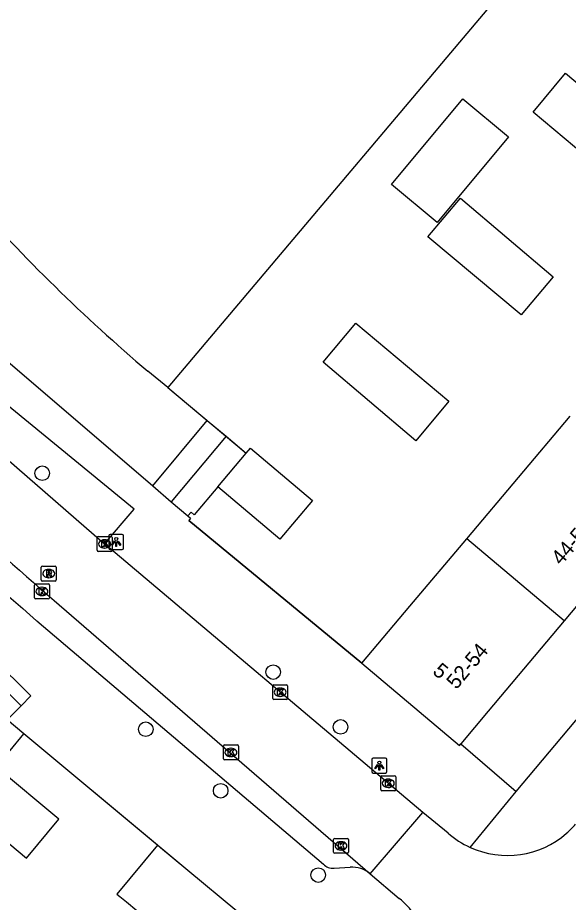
# Model space of a CAD drawing. Extents: x 162532 to 163264, y 381233 to 382042.
# Drawn here: x 162954.6 to 162991.6, y 381669.2 to 381728.5 of the extents above; entities that cross this region are included whole.
import ezdxf

# ---------------------------------------------------------------- set-up
doc = ezdxf.new("R2010")
doc.units = 0
for name, color, linetype in [('IMGEO_Boom', 7, 'Continuous'), ('IMGEO_Groenvoorziening', 7, 'Continuous'), ('IMGEO_Hek', 7, 'Continuous'), ('IMGEO_Kolk', 7, 'Continuous'), ('IMGEO_Lichtpunt', 7, 'Continuous'), ('IMGEO_Muur', 7, 'Continuous'), ('IMGEO_Pand', 7, 'Continuous'), ('IMGEO_Pand_nummerreeks', 7, 'Continuous'), ('IMGEO_Rijbaan_lokaal_open', 7, 'Continuous'), ('IMGEO_Rioolput', 7, 'Continuous'), ('IMGEO_Voetpad_open', 7, 'Continuous')]:
    doc.layers.add(name, color=color, linetype=linetype)

msp = doc.modelspace()

# ---------------------------------------------------------------- linework, layer by layer
at = {"layer": 'IMGEO_Boom'}
for centre in [(162956.297, 381697.954), (162971.791, 381684.612), (162976.31, 381680.937), (162963.243, 381680.782), (162968.27, 381676.657), (162974.813, 381670.995)]:
    msp.add_circle(centre, 0.489, dxfattribs=at)
at = {"layer": 'IMGEO_Groenvoorziening'}
for points in [[(162964.729, 381703.699), (162967.366, 381701.497)], [(162968.629, 381700.443), (162969.987, 381699.309)], [(162968.077, 381697.044), (162966.49, 381695.158), (162966.278, 381695.34), (162966.063, 381695.095)]]:
    msp.add_lwpolyline(points, dxfattribs=at)
at = {"layer": 'IMGEO_Hek'}
msp.add_lwpolyline([(162964.729, 381703.699), (162969.987, 381699.309)], dxfattribs=at)
at = {"layer": 'IMGEO_Kolk'}
for p, q in [((162959.977, 381692.785), (162959.977, 381693.637)), ((162960.052, 381693.711), (162960.904, 381693.711)), ((162960.465, 381693.491), (162960.49, 381693.491)), ((162960.978, 381693.637), (162960.978, 381692.785)), ((162960.904, 381692.711), (162960.052, 381692.711)), ((162960.488, 381692.931), (162960.463, 381692.931)), ((162955.776, 381689.603), (162955.776, 381690.455)), ((162955.851, 381690.529), (162956.703, 381690.529)), ((162956.777, 381690.455), (162956.777, 381689.603)), ((162956.287, 381689.749), (162956.262, 381689.749)), ((162956.264, 381690.309), (162956.289, 381690.309)), ((162956.703, 381689.529), (162955.851, 381689.529)), ((162971.758, 381682.841), (162971.758, 381683.693)), ((162971.833, 381683.767), (162972.685, 381683.767)), ((162972.246, 381683.547), (162972.271, 381683.547)), ((162972.759, 381683.693), (162972.759, 381682.841)), ((162972.685, 381682.767), (162971.833, 381682.767)), ((162972.269, 381682.987), (162972.244, 381682.987)), ((162968.453, 381678.8), (162968.453, 381679.652)), ((162968.528, 381679.726), (162969.38, 381679.726)), ((162969.454, 381679.652), (162969.454, 381678.8)), ((162968.941, 381679.506), (162968.966, 381679.506)), ((162969.38, 381678.726), (162968.528, 381678.726)), ((162968.964, 381678.946), (162968.939, 381678.946)), ((162979.01, 381676.729), (162979.01, 381677.581)), ((162979.085, 381677.655), (162979.937, 381677.655)), ((162979.498, 381677.435), (162979.523, 381677.435)), ((162980.011, 381677.581), (162980.011, 381676.729)), ((162979.521, 381676.875), (162979.496, 381676.875)), ((162979.937, 381676.655), (162979.085, 381676.655)), ((162975.842, 381672.532), (162975.842, 381673.384)), ((162975.917, 381673.458), (162976.769, 381673.458)), ((162976.33, 381673.238), (162976.355, 381673.238)), ((162976.843, 381673.384), (162976.843, 381672.532)), ((162976.353, 381672.678), (162976.328, 381672.678)), ((162976.769, 381672.458), (162975.917, 381672.458))]:
    msp.add_line(p, q, dxfattribs=at)
for points in [[(162959.977, 381692.785), (162959.977, 381693.637)], [(162960.052, 381693.711), (162960.904, 381693.711)], [(162960.298, 381693.411), (162960.421, 381693.411), (162960.421, 381693.26), (162960.551, 381693.411), (162960.715, 381693.411), (162960.569, 381693.26), (162960.722, 381693.011), (162960.57, 381693.011), (162960.485, 381693.175), (162960.421, 381693.108), (162960.421, 381693.011), (162960.298, 381693.011), (162960.298, 381693.411)], [(162960.978, 381693.637), (162960.978, 381692.785)], [(162960.904, 381692.711), (162960.052, 381692.711)], [(162955.776, 381689.603), (162955.776, 381690.455)], [(162955.851, 381690.529), (162956.703, 381690.529)], [(162956.777, 381690.455), (162956.777, 381689.603)], [(162956.097, 381690.229), (162956.22, 381690.229), (162956.22, 381690.078), (162956.35, 381690.229), (162956.514, 381690.229), (162956.368, 381690.078), (162956.521, 381689.829), (162956.369, 381689.829), (162956.284, 381689.993), (162956.22, 381689.926), (162956.22, 381689.829), (162956.097, 381689.829), (162956.097, 381690.229)], [(162956.703, 381689.529), (162955.851, 381689.529)], [(162971.758, 381682.841), (162971.758, 381683.693)], [(162971.833, 381683.767), (162972.685, 381683.767)], [(162972.079, 381683.467), (162972.202, 381683.467), (162972.202, 381683.316), (162972.332, 381683.467), (162972.496, 381683.467), (162972.35, 381683.316), (162972.503, 381683.067), (162972.351, 381683.067), (162972.266, 381683.231), (162972.202, 381683.164), (162972.202, 381683.067), (162972.079, 381683.067), (162972.079, 381683.467)], [(162972.759, 381683.693), (162972.759, 381682.841)], [(162972.685, 381682.767), (162971.833, 381682.767)], [(162968.453, 381678.8), (162968.453, 381679.652)], [(162968.528, 381679.726), (162969.38, 381679.726)], [(162969.454, 381679.652), (162969.454, 381678.8)], [(162968.774, 381679.426), (162968.897, 381679.426), (162968.897, 381679.275), (162969.027, 381679.426), (162969.191, 381679.426), (162969.045, 381679.275), (162969.198, 381679.026), (162969.046, 381679.026), (162968.961, 381679.19), (162968.897, 381679.123), (162968.897, 381679.026), (162968.774, 381679.026), (162968.774, 381679.426)], [(162969.38, 381678.726), (162968.528, 381678.726)], [(162979.01, 381676.729), (162979.01, 381677.581)], [(162979.085, 381677.655), (162979.937, 381677.655)], [(162979.331, 381677.355), (162979.454, 381677.355), (162979.454, 381677.204), (162979.584, 381677.355), (162979.748, 381677.355), (162979.602, 381677.204), (162979.755, 381676.955), (162979.603, 381676.955), (162979.518, 381677.119), (162979.454, 381677.052), (162979.454, 381676.955), (162979.331, 381676.955), (162979.331, 381677.355)], [(162980.011, 381677.581), (162980.011, 381676.729)], [(162979.937, 381676.655), (162979.085, 381676.655)], [(162975.842, 381672.532), (162975.842, 381673.384)], [(162975.917, 381673.458), (162976.769, 381673.458)], [(162976.163, 381673.158), (162976.286, 381673.158), (162976.286, 381673.007), (162976.416, 381673.158), (162976.58, 381673.158), (162976.434, 381673.007), (162976.587, 381672.758), (162976.435, 381672.758), (162976.35, 381672.922), (162976.286, 381672.855), (162976.286, 381672.758), (162976.163, 381672.758), (162976.163, 381673.158)], [(162976.843, 381673.384), (162976.843, 381672.532)], [(162976.769, 381672.458), (162975.917, 381672.458)]]:
    msp.add_lwpolyline(points, dxfattribs=at)
for centre, start, end in [((162960.054, 381693.635), 91.55205, 178.44795), ((162960.054, 381693.635), 91.55205, 178.44795), ((162960.902, 381693.635), 1.55205, 88.44795), ((162960.902, 381693.635), 1.55205, 88.44795), ((162960.054, 381692.787), 181.55205, 268.44795), ((162960.054, 381692.787), 181.55205, 268.44795), ((162960.902, 381692.787), 271.55205, 358.44795), ((162960.902, 381692.787), 271.55205, 358.44795), ((162955.853, 381690.453), 91.55205, 178.44795), ((162955.853, 381690.453), 91.55205, 178.44795), ((162956.701, 381690.453), 1.55205, 88.44795), ((162956.701, 381690.453), 1.55205, 88.44795), ((162955.853, 381689.605), 181.55205, 268.44795), ((162955.853, 381689.605), 181.55205, 268.44795), ((162956.701, 381689.605), 271.55205, 358.44795), ((162956.701, 381689.605), 271.55205, 358.44795), ((162971.835, 381683.691), 91.55205, 178.44795), ((162971.835, 381683.691), 91.55205, 178.44795), ((162972.683, 381683.691), 1.55205, 88.44795), ((162972.683, 381683.691), 1.55205, 88.44795), ((162971.835, 381682.843), 181.55205, 268.44795), ((162971.835, 381682.843), 181.55205, 268.44795), ((162972.683, 381682.843), 271.55205, 358.44795), ((162972.683, 381682.843), 271.55205, 358.44795), ((162968.53, 381679.65), 91.55205, 178.44795), ((162968.53, 381679.65), 91.55205, 178.44795), ((162969.378, 381679.65), 1.55205, 88.44795), ((162969.378, 381679.65), 1.55205, 88.44795), ((162968.53, 381678.802), 181.55205, 268.44795), ((162968.53, 381678.802), 181.55205, 268.44795), ((162969.378, 381678.802), 271.55205, 358.44795), ((162969.378, 381678.802), 271.55205, 358.44795), ((162979.087, 381677.579), 91.55205, 178.44795), ((162979.087, 381677.579), 91.55205, 178.44795), ((162979.935, 381677.579), 1.55205, 88.44795), ((162979.935, 381677.579), 1.55205, 88.44795), ((162979.087, 381676.731), 181.55205, 268.44795), ((162979.087, 381676.731), 181.55205, 268.44795), ((162979.935, 381676.731), 271.55205, 358.44795), ((162979.935, 381676.731), 271.55205, 358.44795), ((162975.919, 381673.382), 91.55205, 178.44795), ((162975.919, 381673.382), 91.55205, 178.44795), ((162976.767, 381673.382), 1.55205, 88.44795), ((162976.767, 381673.382), 1.55205, 88.44795), ((162975.919, 381672.534), 181.55205, 268.44795), ((162975.919, 381672.534), 181.55205, 268.44795), ((162976.767, 381672.534), 271.55205, 358.44795), ((162976.767, 381672.534), 271.55205, 358.44795)]:
    msp.add_arc(centre, 0.0765, start, end, dxfattribs=at)
for centre, major_axis, ratio, start_param, end_param in [((162960.464, 381693.211), (-0.387, 0.002), 0.722429, 4.712389, 7.853982), ((162960.489, 381693.211), (-0.39, 0.002), 0.717154, 1.570796, 4.712389), ((162956.263, 381690.029), (-0.387, 0.002), 0.722429, 4.712389, 7.853982), ((162956.288, 381690.029), (-0.39, 0.002), 0.717154, 1.570796, 4.712389), ((162972.245, 381683.267), (-0.387, 0.002), 0.722429, 4.712389, 7.853982), ((162972.27, 381683.267), (-0.39, 0.002), 0.717154, 1.570796, 4.712389), ((162968.94, 381679.226), (-0.387, 0.002), 0.722429, 4.712389, 7.853982), ((162968.965, 381679.226), (-0.39, 0.002), 0.717154, 1.570796, 4.712389), ((162979.497, 381677.155), (-0.387, 0.002), 0.722429, 4.712389, 7.853982), ((162979.522, 381677.155), (-0.39, 0.002), 0.717154, 1.570796, 4.712389), ((162976.329, 381672.958), (-0.387, 0.002), 0.722429, 4.712389, 7.853982), ((162976.354, 381672.958), (-0.39, 0.002), 0.717154, 1.570796, 4.712389)]:
    msp.add_ellipse(centre, major_axis=major_axis, ratio=ratio, start_param=start_param, end_param=end_param, dxfattribs=at)
at = {"layer": 'IMGEO_Lichtpunt'}
for p, q in [((162960.762, 381693.746), (162960.762, 381692.939)), ((162960.762, 381693.746), (162960.762, 381692.939)), ((162961.664, 381693.841), (162960.856, 381693.841)), ((162961.664, 381693.841), (162960.856, 381693.841)), ((162961.758, 381692.939), (162961.758, 381693.746)), ((162961.758, 381692.939), (162961.758, 381693.746)), ((162960.856, 381692.845), (162961.664, 381692.845)), ((162960.856, 381692.845), (162961.664, 381692.845)), ((162978.415, 381678.746), (162978.415, 381677.939)), ((162978.415, 381678.746), (162978.415, 381677.939)), ((162979.317, 381678.841), (162978.509, 381678.841)), ((162979.317, 381678.841), (162978.509, 381678.841)), ((162979.411, 381677.939), (162979.411, 381678.746)), ((162979.411, 381677.939), (162979.411, 381678.746)), ((162978.509, 381677.845), (162979.317, 381677.845)), ((162978.509, 381677.845), (162979.317, 381677.845))]:
    msp.add_line(p, q, dxfattribs=at)
for points in [[(162961.136, 381693.41), (162961.175, 381693.382), (162960.987, 381693.12), (162960.949, 381693.147), (162961.136, 381693.41)], [(162961.238, 381693.362), (162961.285, 381693.362), (162961.285, 381693.04), (162961.238, 381693.04), (162961.238, 381693.362)], [(162961.348, 381693.382), (162961.386, 381693.409), (162961.573, 381693.147), (162961.534, 381693.119), (162961.348, 381693.382)], [(162978.789, 381678.41), (162978.828, 381678.382), (162978.64, 381678.12), (162978.602, 381678.147), (162978.789, 381678.41)], [(162978.891, 381678.362), (162978.938, 381678.362), (162978.938, 381678.04), (162978.891, 381678.04), (162978.891, 381678.362)], [(162979.001, 381678.382), (162979.039, 381678.409), (162979.226, 381678.147), (162979.187, 381678.119), (162979.001, 381678.382)]]:
    msp.add_lwpolyline(points, dxfattribs=at)
for centre in [(162961.261, 381693.544), (162978.914, 381678.544)]:
    msp.add_circle(centre, 0.0994, dxfattribs=at)
for centre, start, end in [((162960.856, 381693.746), 90, 180), ((162960.856, 381693.746), 90, 180), ((162961.664, 381693.746), 0, 90), ((162961.664, 381693.746), 0, 90), ((162960.856, 381692.939), 180, 270), ((162960.856, 381692.939), 180, 270), ((162961.664, 381692.939), 270, 0), ((162961.664, 381692.939), 270, 360), ((162978.509, 381678.746), 90, 180), ((162978.509, 381678.746), 90, 180), ((162979.317, 381678.746), 0, 90), ((162979.317, 381678.746), 0, 90), ((162978.509, 381677.939), 180, 270), ((162978.509, 381677.939), 180, 270), ((162979.317, 381677.939), 270, 0), ((162979.317, 381677.939), 270, 360)]:
    msp.add_arc(centre, 0.0946, start, end, dxfattribs=at)
at = {"layer": 'IMGEO_Muur'}
for points in [[(162977.742, 381685.21), (162966.124, 381694.794)], [(162966.065, 381671.316), (162955.064, 381680.47)]]:
    msp.add_lwpolyline(points, dxfattribs=at)
at = {"layer": 'IMGEO_Pand'}
for points in [[(162990.383, 381734.099), (162964.729, 381703.699)], [(162997.661, 381719.549), (162995.476, 381716.943), (162989.231, 381722.179), (162991.415, 381724.785), (162997.661, 381719.549)], [(162982.794, 381714.785), (162979.737, 381717.33), (162984.52, 381723.075), (162987.577, 381720.53), (162982.794, 381714.785)], [(162990.582, 381711.134), (162988.424, 381708.591), (162982.168, 381713.814), (162984.367, 381716.407), (162990.582, 381711.134)], [(162983.586, 381702.793), (162981.368, 381700.134), (162975.15, 381705.403), (162977.328, 381708.014), (162983.586, 381702.793)], [(162964.729, 381703.699), (162963.382, 381704.799)], [(162984.774, 381693.548), (162991.713, 381701.775)], [(162969.987, 381699.309), (162970.265, 381699.638), (162974.431, 381696.124), (162972.243, 381693.53), (162968.077, 381697.044)], [(162968.077, 381697.044), (162969.987, 381699.309)], [(162998.234, 381696.283), (162991.307, 381688.047)], [(162977.742, 381685.21), (162980.965, 381689.033), (162984.774, 381693.548)], [(162991.307, 381688.047), (162984.774, 381693.548)], [(162991.307, 381688.047), (162986.216, 381681.994), (162984.377, 381679.811)], [(162954.879, 381682.353), (162950.585, 381686.607)], [(162977.742, 381685.21), (162984.283, 381679.699), (162984.377, 381679.811)], [(162953.935, 381681.41), (162954.879, 381682.353)], [(162951.04, 381675.633), (162955.245, 381672.135), (162957.413, 381674.741), (162953.208, 381678.239)], [(162964.038, 381673.002), (162961.309, 381669.723), (162961.513, 381669.553), (162961.939, 381669.199), (162963.336, 381668.037), (162959.478, 381663.4)], [(162972.63, 381665.855), (162966.065, 381671.316), (162964.242, 381672.832), (162964.038, 381673.002)]]:
    msp.add_lwpolyline(points, dxfattribs=at)
msp.add_arc((163040.327, 381795.497), 118.939, 221.57083, 229.68985, dxfattribs=at)
at = {"layer": 'IMGEO_Rijbaan_lokaal_open'}
for points in [[(162936.622, 381716.371), (162938.106, 381714.679), (162947.991, 381704.075), (162960.478, 381693.211)], [(162981.843, 381675.2), (162960.478, 381693.211)], [(162957.099, 381689.422), (162978.305, 381671.073)], [(162978.305, 381671.073), (162981.843, 381675.2)], [(162983.522, 381673.814), (162981.843, 381675.2)], [(162978.305, 381671.073), (162980.244, 381669.431)]]:
    msp.add_lwpolyline(points, dxfattribs=at)
for centre, radius, start, end in [((163191.822, 381961.768), 359.537, 226.1006, 229.24335), ((162987.545, 381678.298), 5.968, 311.14455, 319.41994), ((162987.469, 381678.283), 5.962, 228.54989, 245.58193), ((162987.503, 381678.333), 6.022, 245.48188, 311.22949), ((162976.477, 381664.764), 5.997, 36.51494, 51.08809)]:
    msp.add_arc(centre, radius, start, end, dxfattribs=at)
at = {"layer": 'IMGEO_Rioolput'}
for p, q in [((162956.235, 381690.797), (162956.235, 381691.649)), ((162956.31, 381691.723), (162957.162, 381691.723)), ((162957.236, 381691.649), (162957.236, 381690.797)), ((162956.746, 381690.943), (162956.721, 381690.943)), ((162956.723, 381691.503), (162956.748, 381691.503)), ((162957.162, 381690.723), (162956.31, 381690.723))]:
    msp.add_line(p, q, dxfattribs=at)
for points in [[(162956.235, 381690.797), (162956.235, 381691.649)], [(162956.31, 381691.723), (162957.162, 381691.723)], [(162957.236, 381691.649), (162957.236, 381690.797)], [(162956.824, 381691.421), (162956.572, 381691.423), (162956.572, 381691.023)], [(162956.572, 381691.023), (162956.696, 381691.023), (162956.696, 381691.185), (162956.707, 381691.185)], [(162956.75, 381691.342), (162956.696, 381691.342), (162956.696, 381691.261)], [(162956.696, 381691.261), (162956.748, 381691.261)], [(162956.754, 381691.156), (162956.825, 381691.023), (162956.965, 381691.023), (162956.9, 381691.149)], [(162957.162, 381690.723), (162956.31, 381690.723)]]:
    msp.add_lwpolyline(points, dxfattribs=at)
for centre, radius, start, end in [((162956.312, 381691.647), 0.0765, 91.55205, 178.44795), ((162956.312, 381691.647), 0.0765, 91.55205, 178.44795), ((162957.16, 381691.647), 0.0765, 1.55205, 88.44795), ((162957.16, 381691.647), 0.0765, 1.55205, 88.44795), ((162956.706, 381691.132), 0.0533, 26.02933, 88.69889), ((162956.732, 381691.45), 0.19, 274.7715, 282.96867), ((162956.756, 381691.246), 0.0964, 77.00612, 93.18647), ((162956.77, 381691.303), 0.0378, 276.66336, 79.67722), ((162956.823, 381691.311), 0.109, 350.36119, 89.41601), ((162956.821, 381691.311), 0.112, 277.58423, 350.98172), ((162956.805, 381691.096), 0.108, 29.51342, 73.79051), ((162956.312, 381690.799), 0.0765, 181.55205, 268.44795), ((162956.312, 381690.799), 0.0765, 181.55205, 268.44795), ((162957.16, 381690.799), 0.0765, 271.55205, 358.44795), ((162957.16, 381690.799), 0.0765, 271.55205, 358.44795)]:
    msp.add_arc(centre, radius, start, end, dxfattribs=at)
for centre, major_axis, ratio, start_param, end_param in [((162956.722, 381691.223), (-0.387, 0.002), 0.722429, 4.712389, 7.853982), ((162956.747, 381691.223), (-0.39, 0.002), 0.717154, 1.570796, 4.712389)]:
    msp.add_ellipse(centre, major_axis=major_axis, ratio=ratio, start_param=start_param, end_param=end_param, dxfattribs=at)
at = {"layer": 'IMGEO_Voetpad_open'}
for points in [[(162988.098, 381676.598), (163000, 381690.752), (163049.821, 381750), (163057.405, 381759.019), (163056.336, 381759.96), (163057.544, 381761.374)], [(162960.478, 381693.211), (162962.456, 381695.546), (162953.361, 381702.985), (162947.575, 381708.177), (162939.183, 381717.335), (162933.55, 381724.731), (162930.331, 381730.383), (162928.221, 381736.339), (162926.453, 381736.002)], [(162934.409, 381727.381), (162938.236, 381721.876), (162944.337, 381714.615), (162947.68, 381711.099), (162950.994, 381708.006), (162963.707, 381697.114)], [(162954.879, 381682.353), (162955.541, 381683.015), (162922.637, 381715.61), (162921.981, 381714.947)], [(162963.707, 381697.114), (162967.366, 381701.497)], [(162967.366, 381701.497), (162968.629, 381700.443)], [(162968.629, 381700.443), (162964.956, 381696.043)], [(162963.707, 381697.114), (162964.956, 381696.043)], [(162964.956, 381696.043), (162966.063, 381695.095)], [(162966.063, 381695.095), (162966.243, 381694.942), (162966.124, 381694.794), (162977.742, 381685.21)], [(162955.923, 381688.059), (162975.159, 381671.724)], [(162955.064, 381680.47), (162953.935, 381681.41)], [(162953.208, 381678.239), (162955.064, 381680.47)], [(162964.038, 381673.002), (162955.064, 381680.47)], [(162984.377, 381679.811), (162988.098, 381676.598)], [(162985.004, 381672.854), (162988.098, 381676.598)], [(162975.872, 381671.455), (162976.957, 381671.528)]]:
    msp.add_lwpolyline(points, dxfattribs=at)
for centre, radius, start, end in [((163192.817, 381962.862), 362.816, 226.10415, 229.23694), ((162975.828, 381672.418), 0.964, 226.05396, 272.60515), ((162977.061, 381669.613), 1.918, 49.58206, 93.11505)]:
    msp.add_arc(centre, radius, start, end, dxfattribs=at)

# ---------------------------------------------------------------- texts
at = {"layer": 'IMGEO_Pand_nummerreeks'}
for s, rotation, p in [('44-50', 49.39871, (162991.11, 381691.728)), ('52-54', 49.95326, (162984.088, 381683.404)), ('5', 319.8848, (162982.426, 381684.559))]:
    msp.add_text(s, height=1, rotation=rotation, dxfattribs=at).set_placement(p)

doc.saveas('drawing.dxf')
